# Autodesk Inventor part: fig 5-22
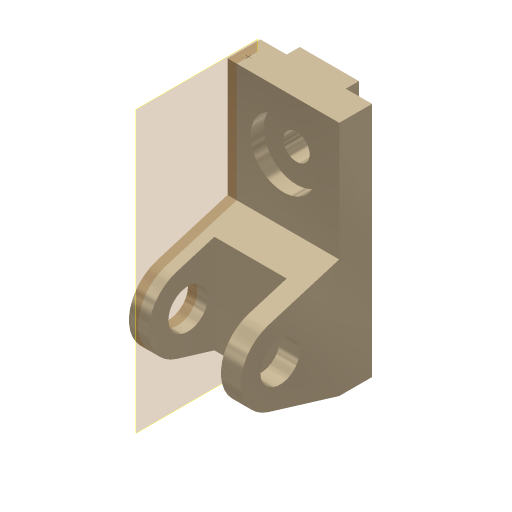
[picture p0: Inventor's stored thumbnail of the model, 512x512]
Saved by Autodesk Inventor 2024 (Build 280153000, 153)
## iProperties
Shininess: 65.0
Angle Display Precision: 2
Document Length Units: 11269
Document Angle Units: 11279
Document Time Units: 11290
Document Mass Units: 11283
Document Length Units Precision: 3
Document Angle Units Precision: 2
Compacted: False
Created: 2001-11
Part Number: fig 5-22
Document SubType Name: Modeling
Designer: Renu Muthoo
Density: 1 g/cm^3
Material: Generic
Appearance: Metal-Titanium (Polished)
Density: 0.0
Volumn: 0.0
Area: 0.0
PropertySet Name: Model Information
Control State: 0
Master: False
Checked Out: False
Author: Renu Muthoo
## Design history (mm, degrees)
sketch "Sketch2"
  geometry: L1 (33.257, 104.664)-(33.257, -75.336); L2 (33.257, -75.336)-(8.257, -75.336); L3 (8.257, -75.336)-(-45.451, -59.045); L4 (-45.451, -1.628)-(8.257, 14.664); L5 (8.257, 14.664)-(8.257, 104.664); L6 (8.257, 104.664)-(33.257, 104.664); C1 r 15 at (-36.743, -30.336); A1 r 30 centre (-36.743, -30.336) between (-45.451, -1.628) and (-45.451, -59.045)
  constraints: 12 end point, 2 centre point, 2 equal length, 2 parallel, 2 point on circle, 2 tangent, 1 coincident, 1 perpendicular, 1 vertical
  dimensions: "d0" = 180 distance of L1.start L1.end; "d1" = 30 radius of A1; "d2" = 25 distance of L5.end L1.start; "d3" = 45 distance from line of L2 A1.centre; "d4" = 70 distance from line of L1 A1.centre; "d5" = 30 diameter of C1
extrude "Extrusion1" new body sketch "Sketch2" distance "d6" = 85; taper "d7" = 0 deg
workplane "Work Plane1"
sketch "Sketch3"
  geometry: L1 (15, 62.364)-(70, 62.364); L2 (70, 62.364)-(70, -52.386); L3 (70, -52.386)-(15, -52.386); L4 (15, -52.386)-(15, 62.364); L5 (0, -45)-(0, -28.708) reference
  constraints: 8 end point, 2 parallel, 1 horizontal, 1 perpendicular
  dimensions: "d8" = 55 distance of L1.start L1.end; "d9" = 15 distance between parallel lines of L5 L4
extrude "Extrusion2" cut sketch "Sketch3" distance "d10" = 50; taper "d11" = 0 deg
sketch "Sketch4"
  geometry: L1 (0, 25)-(85, 25) reference; L2 (0, 0)-(0, 25) reference; L3 (20, 25)-(65, 25); L4 (65, 25)-(65, 35); L5 (65, 35)-(20, 35); L6 (20, 35)-(20, 25)
  constraints: 8 end point, 2 parallel, 1 horizontal, 1 perpendicular, 1 point on line
  dimensions: "d12" = 45 distance of L4.end L5.end; "d13" = 10 distance of L3.end L4.end; "d14" = 20 distance between parallel lines of L2 L6
extrude "Extrusion3" join sketch "Sketch4" stored distance "d15" = 50; taper "d16" = 0 deg
sketch "Sketch5"
  geometry: L1 (85, 0)-(85, 90) reference; L2 (0, 90)-(85, 90) reference; 1 further point
  dimensions: "d17" = 42 distance from line of L2 point (42.5, 48); "d18" = 42.5 distance from line of L1 point (42.5, 48)
hole "Hole1" sketch "Sketch5" diameter "d19" = 20; stored, may be unused: countersink angle "d23" = 82 deg, drill point angle "d25" = 118 deg; dims "d20" = 6, "d21" = 50, "d22" = 10, "d24" = 8
sketch "Sketch11"
  geometry: 1 further point
workplane "Work Plane17"
body "Solid1"
node "Sketch1"
